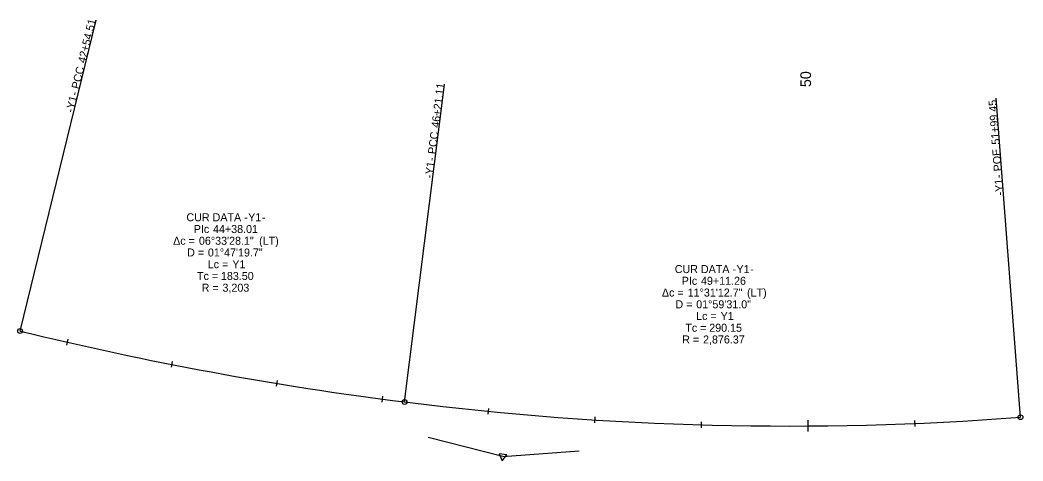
# Model space of a CAD drawing. Extents: x 1182527 to 1186622, y 573661 to 574910.
# Drawn here: x 1185682 to 1186622, y 573661 to 574074 of the extents above; entities that cross this region are included whole.
import ezdxf

# ---------------------------------------------------------------- set-up
doc = ezdxf.new("R2010")
doc.units = 0
for name, color, linetype in [('Default', 7, 'Continuous'), ('E_NCDOT_Vertical_Profile_Ground_Line', 7, 'Continuous'), ('P_HYD_Contour_Major', 7, 'Continuous'), ('P_HYD_Contour_Minor', 7, 'Continuous'), ('P_HYD_TL_Ditch_Mid', 7, 'Continuous'), ('P_HYD_TL_Slope_Stake_Fill', 7, 'Continuous'), ('Scratch_Level_0', 7, 'Continuous')]:
    doc.layers.add(name, color=color, linetype=linetype)

msp = doc.modelspace()

# ---------------------------------------------------------------- linework, layer by layer
at = {"layer": 'Default'}
for q in [(1186064.67, 573683.05), (1186206.22, 573670.64), (1186134.42, 573665.19)]:
    msp.add_line((1186134.42, 573665.19), q, dxfattribs=at)
msp.add_lwpolyline([(1186134.04, 573661.05), (1186138.2, 573666.93), (1186131.03, 573667.59)], close=True, dxfattribs=at)
for centre, radius, start, end in [((1186442.72, 576894.22), 3203, 256.26372, 262.82154), ((1186401.9, 576570.15), 2876.37, 262.82154, 274.34174)]:
    msp.add_arc(centre, radius, start, end, dxfattribs=at)
at = {"layer": 'P_HYD_Contour_Major'}
for p, q in [((1185682.15, 573782.83), (1185753.39, 574074.25)), ((1186042.47, 573716.32), (1186079.96, 574013.97)), ((1186619.66, 573702.03), (1186596.94, 574001.17))]:
    msp.add_line(p, q, dxfattribs=at)
for centre in [(1185682.15, 573782.83), (1186042.47, 573716.32), (1186619.66, 573702.03)]:
    msp.add_circle(centre, 2.25, dxfattribs=at)
at = {"layer": 'P_HYD_TL_Ditch_Mid'}
for p, q in [((1185727.03, 573775.03), (1185725.8, 573769.65)), ((1185824.75, 573754.21), (1185823.68, 573748.79)), ((1185923.07, 573736.45), (1185922.17, 573731)), ((1186021.89, 573721.77), (1186021.17, 573716.29)), ((1186121.13, 573710.29), (1186120.59, 573704.79)), ((1186220.71, 573702.26), (1186220.36, 573696.75)), ((1186320.5, 573697.69), (1186320.34, 573692.17)), ((1186520.26, 573698.98), (1186520.49, 573693.46))]:
    msp.add_line(p, q, dxfattribs=at)
at = {"layer": 'P_HYD_TL_Slope_Stake_Fill'}
msp.add_line((1186420.38, 573699.18), (1186420.45, 573688.56), dxfattribs=at)
at = {"layer": 'Scratch_Level_0'}
for centre, radius, start, end in [((1186442.72, 576894.22), 3203, 256.26372, 262.82154), ((1186401.9, 576570.15), 2876.37, 262.82154, 274.34174)]:
    msp.add_arc(centre, radius, start, end, dxfattribs=at)

# ---------------------------------------------------------------- texts
at = {"layer": 'E_NCDOT_Vertical_Profile_Ground_Line'}
for s, p in [('CUR DATA -', (1185838.07, 573885.66)), ('Y1', (1185895.9, 573885.66)), ('-', (1185908.72, 573885.66)), ('PIc ', (1185844.92, 573874.66)), ('44+38.01', (1185862.97, 573874.66)), ('Δc = ', (1185825.61, 573863.66)), ('06°33\'28.1"', (1185849.78, 573863.66)), (' (LT)', (1185903.38, 573863.66)), ('D = ', (1185838.67, 573852.66)), ('01°47\'19.7"', (1185858.17, 573852.66)), ('Lc = ', (1185858.02, 573841.66)), ('Y1', (1185881.03, 573841.66)), ('CUR DATA -', (1186295.65, 573837.12)), ('Y1', (1186353.49, 573837.12)), ('Tc = ', (1185847.99, 573830.66)), ('183.50', (1185870.41, 573830.66)), ('PIc ', (1186302.17, 573826.12)), ('49+11.26', (1186320.22, 573826.12)), ('-', (1186366.3, 573837.12)), ('R = ', (1185852.35, 573819.66)), ('3,203', (1185871.86, 573819.66)), ('Δc = ', (1186283.58, 573815.12)), ('11°31\'12.7"', (1186307.76, 573815.12)), (' (LT)', (1186360.58, 573815.12)), ('D = ', (1186296.25, 573804.12)), ('01°59\'31.0"', (1186315.76, 573804.12)), ('Lc = ', (1186315.61, 573793.12)), ('Y1', (1186338.62, 573793.12)), ('Tc = ', (1186305.54, 573782.12)), ('290.15', (1186327.96, 573782.12)), ('R = ', (1186302.66, 573771.12)), ('2,876.37', (1186322.16, 573771.12))]:
    msp.add_text(s, height=7.5, dxfattribs=at).set_placement(p)
at = {"layer": 'P_HYD_Contour_Major'}
for s, rotation, p in [('42+54.51', 76.26372, (1185743.4, 574033.4)), ('PCC', 76.26372, (1185737.46, 574009.08)), ('46+21.11', 82.82154, (1186074.8, 573973.02)), ('Y1', 76.26372, (1185732.9, 573990.41)), ('- ', 76.26372, (1185735.94, 574002.86)), ('51+99.45', 94.34174, (1186600.24, 573957.74)), ('-', 76.26372, (1185732.07, 573987.03)), ('PCC', 82.82154, (1186071.67, 573948.18)), ('POE', 94.34174, (1186602.14, 573932.76)), ('Y1', 82.82154, (1186069.27, 573929.12)), ('- ', 82.82154, (1186070.87, 573941.83)), ('-', 82.82154, (1186068.83, 573925.66)), ('- ', 94.34174, (1186602.62, 573926.39)), ('Y1', 94.34174, (1186603.59, 573913.61)), ('-', 94.34174, (1186603.86, 573910.13))]:
    msp.add_text(s, height=7.5, rotation=rotation, dxfattribs=at).set_placement(p)
at = {"layer": 'P_HYD_Contour_Minor'}
msp.add_text('50', height=10, rotation=90.36875, dxfattribs=at).set_placement((1186423.37, 574011.45))

doc.saveas('drawing.dxf')
